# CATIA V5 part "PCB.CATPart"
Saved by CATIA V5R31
Part number: PCB
Source: Unknown
Bounding box of the stored display mesh (mm): x -3.5 to 7.5, y -11.5 to 10, z -1 to 0
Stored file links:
  \\solize.local\damia\dept\DDE_Design\10_order\2305701_JAMA_変換検証STEP3_お手本モデル作成\work\03_東洋電装_スイッチ\10_CATIA_V5\PCB.CATPart
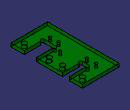
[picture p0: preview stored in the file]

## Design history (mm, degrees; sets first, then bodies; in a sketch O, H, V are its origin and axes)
WSupportSet1: ActiveGrid {3dwsupport RefPoint {point stored without definition}, 3DWOS ({wsupport Support xy-plane, RefPoint {3dwsupport}, GridIn {cartgrid Value 100, Stepbid1 0, Value 100, Stepbid2 0, Direction (1, 0, 0)}, GeometricData ({line type PtDir, Direction (1, 0, 0), Support xy-plane}; {line type PtDir, Direction (0, 1, 0), Support xy-plane})}; {wsupport Support yz-plane, RefPoint {3dwsupport}, GridIn {cartgrid Value 100, Stepbid1 0, Value 100, Stepbid2 0, Direction (0, 1, 0)}, GeometricData ({line type PtDir, Direction (0, 1, 0), Support yz-plane}; {line type PtDir, Direction (0, 0, 1), Support yz-plane})}; {wsupport Support zx-plane, RefPoint {3dwsupport}, GridIn {cartgrid Value 100, Stepbid1 0, Value 100, Stepbid2 0, Direction (0, 0, 1)}, GeometricData ({line type PtDir, Direction (0, 0, 1), Support zx-plane}; {line type PtDir, Direction (1, 0, 0), Support zx-plane})}), GeometricData ({line type PtDir, RefPoint {point stored without definition}, Direction (1, 0, 0), Support xy-plane}; {line type PtDir, RefPoint {point stored without definition}, Direction (0, 1, 0), Support xy-plane}; {line type PtDir, RefPoint {point stored without definition}, Direction (0, 1, 0), Support yz-plane}; {line type PtDir, RefPoint {point stored without definition}, Direction (0, 0, 1), Support yz-plane}; {line type PtDir, RefPoint {point stored without definition}, Direction (0, 0, 1), Support zx-plane}; {line type PtDir, RefPoint {point stored without definition}, Direction (1, 0, 0), Support zx-plane})}
Body1 (main body)
  Solid1 "PartBody": solid without history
